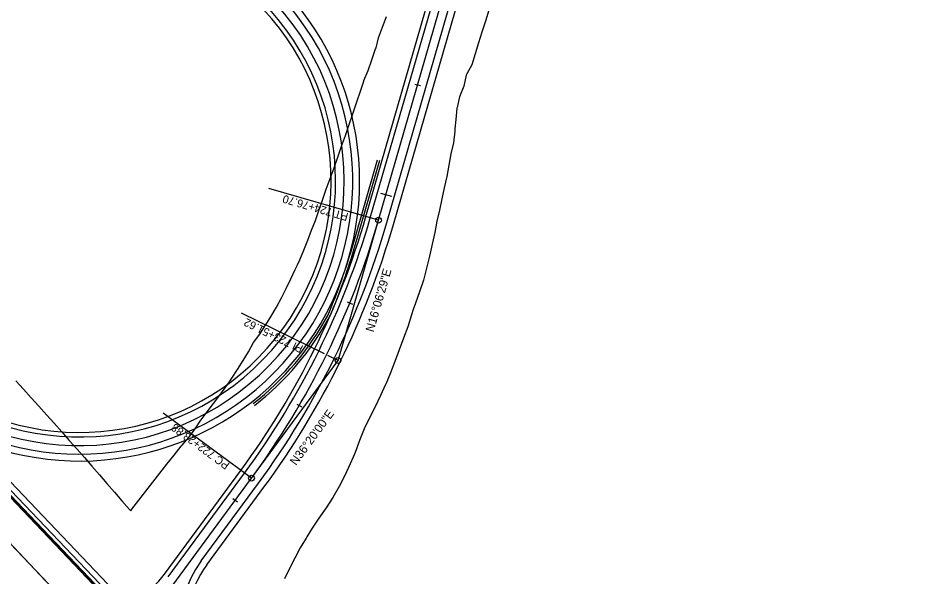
# Model space of a CAD drawing. Extents: x 1300404 to 1323571, y 237813 to 252077.
# Drawn here: x 1311153 to 1311953, y 240595 to 241084 of the extents above; entities that cross this region are included whole.
import ezdxf

# ---------------------------------------------------------------- set-up
doc = ezdxf.new("R2010")
doc.units = 0
for name, color, linetype in [('R_Const Limits', 7, 'Continuous'), ('R_Curb', 7, 'Continuous'), ('R_Future', 7, 'Continuous'), ('R_Horz Alg Annot', 7, 'Continuous'), ('R_Horz Alg Annot Leader', 7, 'Continuous'), ('R_Horz Alg Major Ticks', 7, 'Continuous'), ('R_Horz Alg Minor Ticks', 7, 'Continuous'), ('R_Horz Alg Tangents', 7, 'Continuous'), ('R_Horz Alg Tangents Text', 7, 'Continuous'), ('R_Lane Edge', 7, 'Continuous'), ('R_Proposed', 7, 'Continuous'), ('R_Shoulder', 7, 'Continuous'), ('R_Sidewalk Edge', 7, 'Continuous')]:
    doc.layers.add(name, color=color, linetype=linetype)

msp = doc.modelspace()

# ---------------------------------------------------------------- linework, layer by layer
at = {"layer": 'R_Const Limits'}
for points in [[(1311251.31, 240653.14), (1311252.34, 240654.48), (1311258.42, 240662.43), (1311264.52, 240670.35), (1311270.65, 240678.26), (1311276.74, 240686.19), (1311282.96, 240694.03), (1311289.17, 240701.88), (1311295.49, 240709.64), (1311296.22, 240710.58), (1311302.18, 240717.14), (1311307.63, 240724.85), (1311312.72, 240732.38), (1311318.04, 240739.75), (1311323.55, 240747), (1311329.13, 240754.24), (1311334.56, 240761.58), (1311337.63, 240765.92), (1311337.63, 240765.93), (1311339.76, 240769.09), (1311344.79, 240776.72), (1311349.57, 240784.5), (1311354.22, 240792.37), (1311358.78, 240800.3), (1311364.13, 240807.82), (1311369.23, 240815.52), (1311369.37, 240815.75), (1311374.13, 240823.35), (1311378.85, 240831.29), (1311383.24, 240839.41), (1311387.29, 240847.7), (1311391.33, 240856), (1311395.23, 240864.38), (1311397.07, 240868.37), (1311397.08, 240868.38), (1311399.03, 240872.81), (1311402.68, 240881.31), (1311406.21, 240889.87), (1311409.51, 240898.52), (1311412.73, 240907.22), (1311415.81, 240915.96), (1311419.03, 240924.93), (1311422.31, 240934.39), (1311425.65, 240943.83), (1311429.1, 240953.25), (1311432.51, 240962.67), (1311435.75, 240972.14), (1311438.99, 240981.62), (1311442.24, 240991.09), (1311445.44, 241000.57), (1311448.67, 241010.05), (1311449.29, 241011.9), (1311451.85, 241019.54), (1311455.03, 241029.03), (1311455.21, 241029.58), (1311458.96, 241038.3), (1311462.11, 241047.8), (1311465.46, 241057.24), (1311465.82, 241058.26), (1311468.07, 241066.9), (1311471.45, 241076.33), (1311474.97, 241085.72)], [(1311564.58, 241091.07), (1311561.49, 241081.55), (1311558.4, 241072.03), (1311555.45, 241062.49), (1311555.44, 241062.48), (1311552.59, 241052.89), (1311549.67, 241043.33), (1311545.17, 241035.34), (1311544.69, 241034.36), (1311542.46, 241024.6), (1311538.76, 241015.26), (1311536.65, 241006.06), (1311536.59, 241005.47), (1311535.54, 240995.37), (1311534.82, 240987.2), (1311534.65, 240985.22), (1311533.46, 240975.15), (1311531.22, 240965.39), (1311529.45, 240955.49), (1311527.66, 240945.6), (1311525.48, 240935.82), (1311523.25, 240926.06), (1311521.35, 240916.2), (1311519.03, 240906.46), (1311517.1, 240896.61), (1311515, 240886.31), (1311512.61, 240875.83), (1311510.02, 240865.39), (1311507.27, 240854.99), (1311503.78, 240844.83), (1311500.22, 240834.68), (1311498.32, 240829.38), (1311498.32, 240829.38), (1311496.87, 240824.45), (1311493.62, 240814.17), (1311489.82, 240804.08), (1311486.09, 240793.95), (1311482.24, 240783.86), (1311478.43, 240773.73), (1311474.33, 240764.06), (1311474.19, 240763.78), (1311469.62, 240753.98), (1311464.94, 240744.22), (1311460.1, 240734.54), (1311455.46, 240724.73), (1311451.41, 240714.56), (1311447.49, 240704.25), (1311445.71, 240700.01), (1311445.7, 240700.01), (1311443.18, 240694.12), (1311438.54, 240684.15), (1311433.48, 240674.4), (1311428.12, 240664.82), (1311422.11, 240655.66), (1311415.82, 240646.7), (1311409.97, 240637.86), (1311405.38, 240630.29), (1311404.76, 240629.28), (1311399.38, 240620.82), (1311394.77, 240611.8), (1311390.23, 240602.72), (1311385.79, 240593.58)], [(1311150.76, 240766.85), (1311157.47, 240759.43), (1311164.17, 240752), (1311170.87, 240744.58), (1311177.57, 240737.15), (1311184.27, 240729.72), (1311190.94, 240722.26), (1311197.55, 240714.75), (1311204.16, 240707.24), (1311210.78, 240699.72), (1311217.39, 240692.21), (1311223.93, 240684.63), (1311230.48, 240677.06), (1311237.03, 240669.49), (1311243.59, 240661.93), (1311250.19, 240654.4), (1311251.31, 240653.14)]]:
    msp.add_lwpolyline(points, dxfattribs=at)
at = {"layer": 'R_Curb'}
for p, q in [((1311065.94, 240750.04), (1311239.97, 240567.73)), ((1311067.92, 240748.69), (1311240.13, 240568.28))]:
    msp.add_line(p, q, dxfattribs=at)
at = {"layer": 'R_Future'}
for p, q in [((1311446.03, 240887.11), (1311467.17, 240960.33)), ((1311447.95, 240886.55), (1311469.15, 240959.97))]:
    msp.add_line(p, q, dxfattribs=at)
for centre, radius, start, end in [((1311206.47, 240941.72), 245, 246.68093, 113.15991), ((1311206.47, 240941.72), 239, 234.16397, 118.30111), ((1311206.47, 240941.72), 231.5, 223.66667, 131.16667), ((1311206.47, 240941.72), 231.5, 223.66667, 131.16667), ((1311206.47, 240941.72), 224, 223.66667, 131.16667), ((1311206.47, 240941.72), 220, 236.50529, 138.89832), ((1310910.45, 241041.77), 557.46, 337.01762, 343.89183), ((1310910.45, 241041.77), 559.46, 337.00787, 343.89183), ((1311206.47, 240941.72), 247, 307.93362, 331.5655), ((1311206.47, 240941.72), 249, 307.93362, 331.58744)]:
    msp.add_arc(centre, radius, start, end, dxfattribs=at)
at = {"layer": 'R_Horz Alg Annot Leader'}
for points in [[(1311468.01, 240907.35), (1311371.93, 240935.09)], [(1311420.75, 240790.45), (1311348.2, 240826.18)], [(1311432.57, 240784.63), (1311423.68, 240789.01)], [(1311356.89, 240681.72), (1311279.62, 240738.55)]]:
    msp.add_lwpolyline(points, dxfattribs=at)
at = {"layer": 'R_Horz Alg Major Ticks'}
msp.add_lwpolyline([(1311469.67, 240931.12), (1311479.28, 240928.35)], dxfattribs=at)
at = {"layer": 'R_Horz Alg Minor Ticks'}
for points in [[(1311499.82, 241026.5), (1311504.62, 241025.11)], [(1311440.51, 240835.89), (1311445.14, 240833.99)], [(1311396.48, 240746.58), (1311400.8, 240744.06)], [(1311340.72, 240663.96), (1311344.75, 240661)]]:
    msp.add_lwpolyline(points, dxfattribs=at)
at = {"layer": 'R_Horz Alg Tangents'}
for p, q in [((1311432.57, 240784.63), (1311468.01, 240907.35)), ((1311356.89, 240681.72), (1311432.57, 240784.63))]:
    msp.add_line(p, q, dxfattribs=at)
at = {"layer": 'R_Lane Edge'}
for p, q in [((1311460.8, 240909.43), (1311563.29, 241264.31)), ((1311460.8, 240909.43), (1311563.29, 241264.31)), ((1311475.21, 240905.27), (1311577.7, 241260.15)), ((1310682.55, 241150.26), (1311239.63, 240566.63)), ((1311284.15, 240595.49), (1311350.84, 240686.17)), ((1311313.02, 240609.42), (1311362.93, 240677.28))]:
    msp.add_line(p, q, dxfattribs=at)
for centre, radius, start, end in [((1310779.93, 241106.06), 708.7, 323.66667, 343.89183), ((1310779.93, 241106.06), 723.7, 323.66667, 343.89183), ((1310779.93, 241106.06), 723.7, 323.66667, 343.89183), ((1311393.58, 240550.17), 100, 143.66667, 223.66667)]:
    msp.add_arc(centre, radius, start, end, dxfattribs=at)
at = {"layer": 'R_Proposed'}
for p, q in [((1310151.78, 241665.77), (1311952.58, 239779.15)), ((1310165.59, 241651.3), (1311952.63, 239779.09)), ((1310165.59, 241651.3), (1311952.63, 239779.09)), ((1311468.01, 240907.35), (1311570.49, 241262.23)), ((1311241.2, 240524.43), (1311356.89, 240681.72))]:
    msp.add_line(p, q, dxfattribs=at)
for centre in [(1311468.01, 240907.35), (1311432.57, 240784.63), (1311356.89, 240681.72)]:
    msp.add_circle(centre, 2.5, dxfattribs=at)
msp.add_arc((1310779.93, 241106.06), 716.2, 323.66667, 343.89183, dxfattribs=at)
at = {"layer": 'R_Shoulder'}
for p, q in [((1311456.96, 240910.54), (1311559.45, 241265.42)), ((1311480.98, 240903.6), (1311583.46, 241258.48)), ((1311280.93, 240597.86), (1311347.62, 240688.54)), ((1311317.85, 240605.87), (1311367.76, 240673.73))]:
    msp.add_line(p, q, dxfattribs=at)
for centre, radius, start, end in [((1310779.93, 241106.06), 704.7, 323.66667, 343.89183), ((1310779.93, 241106.06), 729.7, 323.66667, 343.89183), ((1311393.58, 240550.17), 94, 143.66667, 192.57952), ((1311223.73, 240639.92), 71, 297.63688, 323.66667)]:
    msp.add_arc(centre, radius, start, end, dxfattribs=at)
at = {"layer": 'R_Sidewalk Edge'}
for p, q in [((1310928.27, 240906.59), (1311249.89, 240569.63)), ((1310928.1, 240899.52), (1311244.64, 240567.9))]:
    msp.add_line(p, q, dxfattribs=at)

# ---------------------------------------------------------------- texts
at = {"layer": 'R_Horz Alg Annot'}
for s, rotation, p in [('PT 724+76.70', 163.89183, (1311442.1, 240913.27)), ('PI 723+51.62', 153.77925, (1311402.73, 240797.18)), ('PC 722+23.88', 143.66667, (1311338.41, 240694.41))]:
    msp.add_text(s, height=7, rotation=rotation, dxfattribs=at).set_placement(p)
at = {"layer": 'R_Horz Alg Tangents Text'}
for s, rotation, p in [('N16%%d06\'29"E', 73.89183, (1311463.62, 240809.02)), ('N36%%d20\'00"E', 53.66667, (1311395.89, 240692.25))]:
    msp.add_text(s, height=7.5, rotation=rotation, dxfattribs=at).set_placement(p)

doc.saveas('drawing.dxf')
